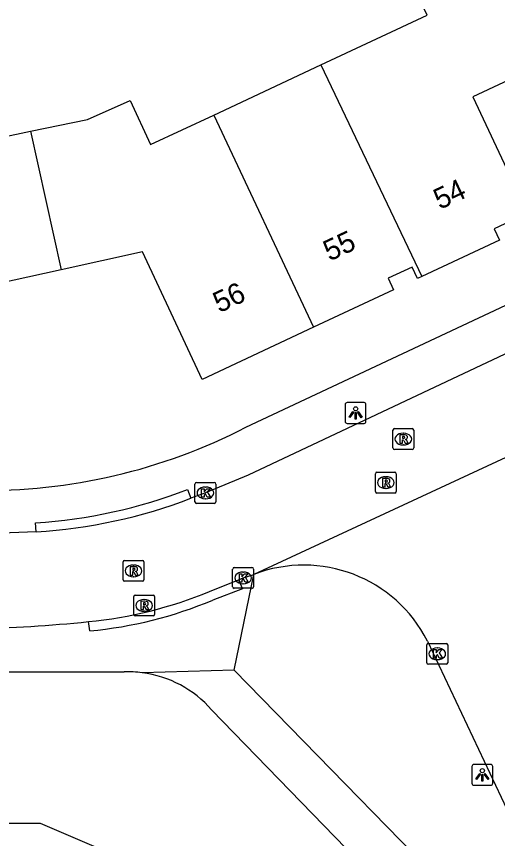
# Model space of a CAD drawing. Extents: x 162880 to 165536, y 384011 to 385179.
# Drawn here: x 163852.88 to 163875.95, y 384301.21 to 384340.61 of the extents above; entities that cross this region are included whole.
import ezdxf

# ---------------------------------------------------------------- set-up
doc = ezdxf.new("R2010")
doc.units = 0
for name, color, linetype in [('IMGEO_Kolk', 7, 'Continuous'), ('IMGEO_Lichtpunt', 7, 'Continuous'), ('IMGEO_Pand', 7, 'Continuous'), ('IMGEO_Pand_nummerreeks', 7, 'Continuous'), ('IMGEO_Rijbaan_lokaal_gesloten', 7, 'Continuous'), ('IMGEO_Rioolput', 7, 'Continuous'), ('IMGEO_Voetpad_open', 7, 'Continuous')]:
    doc.layers.add(name, color=color, linetype=linetype)

msp = doc.modelspace()

# ---------------------------------------------------------------- linework, layer by layer
at = {"layer": 'IMGEO_Kolk'}
for p, q in [((163861.438, 384317.351), (163861.438, 384318.203)), ((163861.513, 384318.277), (163862.365, 384318.277)), ((163861.926, 384318.057), (163861.951, 384318.057)), ((163862.439, 384318.203), (163862.439, 384317.351)), ((163862.365, 384317.277), (163861.513, 384317.277)), ((163861.949, 384317.497), (163861.924, 384317.497)), ((163863.246, 384313.28), (163863.246, 384314.132)), ((163863.321, 384314.206), (163864.173, 384314.206)), ((163864.247, 384314.132), (163864.247, 384313.28)), ((163863.734, 384313.986), (163863.759, 384313.986)), ((163863.757, 384313.426), (163863.732, 384313.426)), ((163864.173, 384313.206), (163863.321, 384313.206)), ((163872.558, 384309.641), (163872.558, 384310.493)), ((163872.633, 384310.567), (163873.485, 384310.567)), ((163873.559, 384310.493), (163873.559, 384309.641)), ((163873.046, 384310.347), (163873.071, 384310.347)), ((163873.069, 384309.787), (163873.044, 384309.787)), ((163873.485, 384309.567), (163872.633, 384309.567))]:
    msp.add_line(p, q, dxfattribs=at)
for points in [[(163861.438, 384317.351), (163861.438, 384318.203)], [(163861.513, 384318.277), (163862.365, 384318.277)], [(163861.759, 384317.977), (163861.882, 384317.977), (163861.882, 384317.826), (163862.012, 384317.977), (163862.176, 384317.977), (163862.03, 384317.826), (163862.183, 384317.577), (163862.031, 384317.577), (163861.946, 384317.741), (163861.882, 384317.674), (163861.882, 384317.577), (163861.759, 384317.577), (163861.759, 384317.977)], [(163862.439, 384318.203), (163862.439, 384317.351)], [(163862.365, 384317.277), (163861.513, 384317.277)], [(163863.246, 384313.28), (163863.246, 384314.132)], [(163863.321, 384314.206), (163864.173, 384314.206)], [(163864.247, 384314.132), (163864.247, 384313.28)], [(163863.567, 384313.906), (163863.69, 384313.906), (163863.69, 384313.755), (163863.82, 384313.906), (163863.984, 384313.906), (163863.838, 384313.755), (163863.991, 384313.506), (163863.839, 384313.506), (163863.754, 384313.67), (163863.69, 384313.603), (163863.69, 384313.506), (163863.567, 384313.506), (163863.567, 384313.906)], [(163864.173, 384313.206), (163863.321, 384313.206)], [(163872.558, 384309.641), (163872.558, 384310.493)], [(163872.633, 384310.567), (163873.485, 384310.567)], [(163873.559, 384310.493), (163873.559, 384309.641)], [(163872.879, 384310.267), (163873.002, 384310.267), (163873.002, 384310.116), (163873.132, 384310.267), (163873.296, 384310.267), (163873.15, 384310.116), (163873.303, 384309.867), (163873.151, 384309.867), (163873.066, 384310.031), (163873.002, 384309.964), (163873.002, 384309.867), (163872.879, 384309.867), (163872.879, 384310.267)], [(163873.485, 384309.567), (163872.633, 384309.567)]]:
    msp.add_lwpolyline(points, dxfattribs=at)
for centre, start, end in [((163861.515, 384318.201), 91.552, 178.448), ((163861.515, 384318.201), 91.552, 178.448), ((163862.363, 384318.201), 1.552, 88.448), ((163862.363, 384318.201), 1.552, 88.448), ((163861.515, 384317.353), 181.552, 268.448), ((163861.515, 384317.353), 181.552, 268.448), ((163862.363, 384317.353), 271.552, 358.448), ((163862.363, 384317.353), 271.552, 358.448), ((163863.323, 384314.13), 91.552, 178.448), ((163863.323, 384314.13), 91.552, 178.448), ((163864.171, 384314.13), 1.552, 88.448), ((163864.171, 384314.13), 1.552, 88.448), ((163863.323, 384313.282), 181.552, 268.448), ((163863.323, 384313.282), 181.552, 268.448), ((163864.171, 384313.282), 271.552, 358.448), ((163864.171, 384313.282), 271.552, 358.448), ((163872.635, 384310.491), 91.552, 178.448), ((163872.635, 384310.491), 91.552, 178.448), ((163873.483, 384310.491), 1.552, 88.448), ((163873.483, 384310.491), 1.552, 88.448), ((163872.635, 384309.643), 181.552, 268.448), ((163872.635, 384309.643), 181.552, 268.448), ((163873.483, 384309.643), 271.552, 358.448), ((163873.483, 384309.643), 271.552, 358.448)]:
    msp.add_arc(centre, 0.0765, start, end, dxfattribs=at)
for centre, major_axis, ratio, start_param, end_param in [((163861.925, 384317.777), (-0.387, 0.002), 0.722429, 4.712389, 7.853982), ((163861.95, 384317.777), (-0.39, 0.002), 0.717154, 1.570796, 4.712389), ((163863.733, 384313.706), (-0.387, 0.002), 0.722429, 4.712389, 7.853982), ((163863.758, 384313.706), (-0.39, 0.002), 0.717154, 1.570796, 4.712389), ((163873.045, 384310.067), (-0.387, 0.002), 0.722429, 4.712389, 7.853982), ((163873.07, 384310.067), (-0.39, 0.002), 0.717154, 1.570796, 4.712389)]:
    msp.add_ellipse(centre, major_axis=major_axis, ratio=ratio, start_param=start_param, end_param=end_param, dxfattribs=at)
at = {"layer": 'IMGEO_Lichtpunt'}
for p, q in [((163868.642, 384322.011), (163868.642, 384321.204)), ((163868.642, 384322.011), (163868.642, 384321.204)), ((163869.544, 384322.106), (163868.736, 384322.106)), ((163869.544, 384322.106), (163868.736, 384322.106)), ((163869.638, 384321.204), (163869.638, 384322.011)), ((163869.638, 384321.204), (163869.638, 384322.011)), ((163868.736, 384321.11), (163869.544, 384321.11)), ((163868.736, 384321.11), (163869.544, 384321.11)), ((163874.721, 384304.669), (163874.721, 384303.862)), ((163874.721, 384304.669), (163874.721, 384303.862)), ((163875.623, 384304.764), (163874.815, 384304.764)), ((163875.623, 384304.764), (163874.815, 384304.764)), ((163875.717, 384303.862), (163875.717, 384304.669)), ((163875.717, 384303.862), (163875.717, 384304.669)), ((163874.815, 384303.768), (163875.623, 384303.768)), ((163874.815, 384303.768), (163875.623, 384303.768))]:
    msp.add_line(p, q, dxfattribs=at)
for points in [[(163869.016, 384321.675), (163869.055, 384321.647), (163868.867, 384321.385), (163868.829, 384321.412), (163869.016, 384321.675)], [(163869.118, 384321.627), (163869.165, 384321.627), (163869.165, 384321.305), (163869.118, 384321.305), (163869.118, 384321.627)], [(163869.228, 384321.647), (163869.266, 384321.674), (163869.453, 384321.412), (163869.414, 384321.384), (163869.228, 384321.647)], [(163875.095, 384304.333), (163875.134, 384304.305), (163874.946, 384304.043), (163874.908, 384304.07), (163875.095, 384304.333)], [(163875.197, 384304.285), (163875.244, 384304.285), (163875.244, 384303.963), (163875.197, 384303.963), (163875.197, 384304.285)], [(163875.307, 384304.305), (163875.345, 384304.332), (163875.532, 384304.07), (163875.493, 384304.042), (163875.307, 384304.305)]]:
    msp.add_lwpolyline(points, dxfattribs=at)
for centre in [(163869.141, 384321.809), (163875.22, 384304.467)]:
    msp.add_circle(centre, 0.0994, dxfattribs=at)
for centre, start, end in [((163868.736, 384322.011), 90, 180), ((163868.736, 384322.011), 90, 180), ((163869.544, 384322.011), 0, 90), ((163869.544, 384322.011), 0, 90), ((163868.736, 384321.204), 180, 270), ((163868.736, 384321.204), 180, 270), ((163869.544, 384321.204), 270, 0), ((163869.544, 384321.204), 270, 360), ((163874.815, 384304.669), 90, 180), ((163874.815, 384304.669), 90, 180), ((163875.623, 384304.669), 0, 90), ((163875.623, 384304.669), 0, 90), ((163874.815, 384303.862), 180, 270), ((163874.815, 384303.862), 180, 270), ((163875.623, 384303.862), 270, 0), ((163875.623, 384303.862), 270, 360)]:
    msp.add_arc(centre, 0.0946, start, end, dxfattribs=at)
at = {"layer": 'IMGEO_Pand'}
for points in [[(163867.481, 384338.294), (163872.569, 384340.676), (163871.581, 384342.787), (163873.082, 384343.496), (163874.574, 384344.201)], [(163862.345, 384335.889), (163867.481, 384338.294)], [(163867.481, 384338.294), (163872.318, 384328.154)], [(163877.472, 384338.021), (163874.764, 384336.753), (163877.382, 384331.186), (163875.787, 384330.441), (163876.041, 384329.897), (163872.318, 384328.154)], [(163853.547, 384335.107), (163856.283, 384335.682), (163858.324, 384336.58), (163859.311, 384334.469), (163862.345, 384335.889)], [(163862.345, 384335.889), (163867.129, 384325.724)], [(163845.313, 384332.091), (163850.472, 384332.091), (163850.471, 384334.461), (163853.547, 384335.107)], [(163853.547, 384335.107), (163855.03, 384328.471)], [(163867.129, 384325.724), (163861.777, 384323.218), (163858.915, 384329.331), (163855.03, 384328.471)], [(163872.318, 384328.154), (163872.102, 384328.053), (163871.848, 384328.597), (163870.707, 384328.063), (163870.961, 384327.518), (163867.129, 384325.724)], [(163855.03, 384328.471), (163851.161, 384327.615), (163851.16, 384320.865), (163845.333, 384320.866)], [(163846.47, 384306.152), (163852.357, 384306.156), (163852.36, 384301.956), (163854.02, 384301.957), (163856.929, 384300.707)]]:
    msp.add_lwpolyline(points, dxfattribs=at)
at = {"layer": 'IMGEO_Rijbaan_lokaal_gesloten'}
for points in [[(163879.615, 384325.991), (163863.997, 384318.625), (163861.94, 384317.777), (163861.247, 384317.522)], [(163879.48, 384320.926), (163864.258, 384313.87)], [(163853.829, 384315.916), (163850.892, 384315.8), (163849.869, 384315.76), (163846.65, 384315.767), (163833.677, 384315.759)], [(163862.135, 384313.051), (163863.528, 384313.607)], [(163863.528, 384313.607), (163863.746, 384313.708), (163864.258, 384313.87)], [(163872.582, 384310.677), (163878.295, 384298.593)]]:
    msp.add_lwpolyline(points, dxfattribs=at)
for centre, radius, start, end in [((163852.345, 384340.706), 24.834, 273.4262, 291.0059), ((163866.657, 384307.676), 6.642, 26.8577, 111.1697), ((163854.346, 384332.034), 20.519, 275.5367, 292.3082), ((163850.172, 384369.286), 58.002, 270.61824, 276.09038)]:
    msp.add_arc(centre, radius, start, end, dxfattribs=at)
at = {"layer": 'IMGEO_Rioolput'}
for p, q in [((163870.929, 384319.933), (163870.929, 384320.785)), ((163871.004, 384320.859), (163871.856, 384320.859)), ((163871.93, 384320.785), (163871.93, 384319.933)), ((163871.417, 384320.639), (163871.442, 384320.639)), ((163871.44, 384320.079), (163871.415, 384320.079)), ((163871.856, 384319.859), (163871.004, 384319.859)), ((163870.167, 384318.774), (163871.019, 384318.774)), ((163870.092, 384317.848), (163870.092, 384318.7)), ((163870.58, 384318.554), (163870.605, 384318.554)), ((163871.093, 384318.7), (163871.093, 384317.848)), ((163870.603, 384317.994), (163870.578, 384317.994)), ((163871.019, 384317.774), (163870.167, 384317.774)), ((163857.992, 384313.617), (163857.992, 384314.469)), ((163858.067, 384314.543), (163858.919, 384314.543)), ((163858.993, 384314.469), (163858.993, 384313.617)), ((163858.48, 384314.323), (163858.505, 384314.323)), ((163858.503, 384313.763), (163858.478, 384313.763)), ((163858.919, 384313.543), (163858.067, 384313.543)), ((163858.577, 384312.884), (163859.429, 384312.884)), ((163858.502, 384311.958), (163858.502, 384312.81)), ((163858.99, 384312.664), (163859.015, 384312.664)), ((163859.503, 384312.81), (163859.503, 384311.958)), ((163859.013, 384312.104), (163858.988, 384312.104)), ((163859.429, 384311.884), (163858.577, 384311.884))]:
    msp.add_line(p, q, dxfattribs=at)
for points in [[(163870.929, 384319.933), (163870.929, 384320.785)], [(163871.004, 384320.859), (163871.856, 384320.859)], [(163871.93, 384320.785), (163871.93, 384319.933)], [(163871.518, 384320.557), (163871.266, 384320.559), (163871.266, 384320.159)], [(163871.266, 384320.159), (163871.39, 384320.159), (163871.39, 384320.321), (163871.401, 384320.321)], [(163871.444, 384320.478), (163871.39, 384320.478), (163871.39, 384320.397)], [(163871.39, 384320.397), (163871.442, 384320.397)], [(163871.448, 384320.292), (163871.519, 384320.159), (163871.659, 384320.159), (163871.594, 384320.285)], [(163871.856, 384319.859), (163871.004, 384319.859)], [(163870.167, 384318.774), (163871.019, 384318.774)], [(163870.092, 384317.848), (163870.092, 384318.7)], [(163870.681, 384318.472), (163870.429, 384318.474), (163870.429, 384318.074)], [(163870.607, 384318.393), (163870.553, 384318.393), (163870.553, 384318.312)], [(163871.093, 384318.7), (163871.093, 384317.848)], [(163870.429, 384318.074), (163870.553, 384318.074), (163870.553, 384318.236), (163870.564, 384318.236)], [(163870.553, 384318.312), (163870.605, 384318.312)], [(163870.611, 384318.207), (163870.682, 384318.074), (163870.822, 384318.074), (163870.757, 384318.2)], [(163871.019, 384317.774), (163870.167, 384317.774)], [(163857.992, 384313.617), (163857.992, 384314.469)], [(163858.067, 384314.543), (163858.919, 384314.543)], [(163858.993, 384314.469), (163858.993, 384313.617)], [(163858.581, 384314.241), (163858.329, 384314.243), (163858.329, 384313.843)], [(163858.329, 384313.843), (163858.453, 384313.843), (163858.453, 384314.005), (163858.464, 384314.005)], [(163858.507, 384314.162), (163858.453, 384314.162), (163858.453, 384314.081)], [(163858.453, 384314.081), (163858.505, 384314.081)], [(163858.511, 384313.976), (163858.582, 384313.843), (163858.722, 384313.843), (163858.657, 384313.969)], [(163858.919, 384313.543), (163858.067, 384313.543)], [(163858.577, 384312.884), (163859.429, 384312.884)], [(163858.502, 384311.958), (163858.502, 384312.81)], [(163859.091, 384312.582), (163858.839, 384312.584), (163858.839, 384312.184)], [(163859.017, 384312.503), (163858.963, 384312.503), (163858.963, 384312.422)], [(163859.503, 384312.81), (163859.503, 384311.958)], [(163858.839, 384312.184), (163858.963, 384312.184), (163858.963, 384312.346), (163858.974, 384312.346)], [(163858.963, 384312.422), (163859.015, 384312.422)], [(163859.021, 384312.317), (163859.092, 384312.184), (163859.232, 384312.184), (163859.167, 384312.31)], [(163859.429, 384311.884), (163858.577, 384311.884)]]:
    msp.add_lwpolyline(points, dxfattribs=at)
for centre, radius, start, end in [((163871.006, 384320.783), 0.0765, 91.552, 178.448), ((163871.006, 384320.783), 0.0765, 91.552, 178.448), ((163871.854, 384320.783), 0.0765, 1.552, 88.448), ((163871.854, 384320.783), 0.0765, 1.552, 88.448), ((163871.4, 384320.268), 0.0533, 26.0293, 88.6989), ((163871.426, 384320.586), 0.19, 274.7715, 282.9687), ((163871.45, 384320.382), 0.0964, 77.0061, 93.1865), ((163871.464, 384320.439), 0.0378, 276.6634, 79.6772), ((163871.517, 384320.447), 0.109, 350.3612, 89.416), ((163871.515, 384320.447), 0.112, 277.5842, 350.9817), ((163871.499, 384320.232), 0.108, 29.5134, 73.7905), ((163871.006, 384319.935), 0.0765, 181.552, 268.448), ((163871.006, 384319.935), 0.0765, 181.552, 268.448), ((163871.854, 384319.935), 0.0765, 271.552, 358.448), ((163871.854, 384319.935), 0.0765, 271.552, 358.448), ((163870.169, 384318.698), 0.0765, 91.552, 178.448), ((163870.169, 384318.698), 0.0765, 91.552, 178.448), ((163871.017, 384318.698), 0.0765, 1.552, 88.448), ((163871.017, 384318.698), 0.0765, 1.552, 88.448), ((163870.613, 384318.297), 0.0964, 77.0061, 93.1865), ((163870.627, 384318.354), 0.0378, 276.6634, 79.6772), ((163870.68, 384318.362), 0.109, 350.3612, 89.416), ((163870.678, 384318.362), 0.112, 277.5842, 350.9817), ((163870.563, 384318.183), 0.0533, 26.0293, 88.6989), ((163870.589, 384318.501), 0.19, 274.7715, 282.9687), ((163870.662, 384318.147), 0.108, 29.5134, 73.7905), ((163870.169, 384317.85), 0.0765, 181.552, 268.448), ((163870.169, 384317.85), 0.0765, 181.552, 268.448), ((163871.017, 384317.85), 0.0765, 271.552, 358.448), ((163871.017, 384317.85), 0.0765, 271.552, 358.448), ((163858.069, 384314.467), 0.0765, 91.552, 178.448), ((163858.069, 384314.467), 0.0765, 91.552, 178.448), ((163858.917, 384314.467), 0.0765, 1.552, 88.448), ((163858.917, 384314.467), 0.0765, 1.552, 88.448), ((163858.463, 384313.952), 0.0533, 26.0293, 88.6989), ((163858.489, 384314.27), 0.19, 274.7715, 282.9687), ((163858.513, 384314.066), 0.0964, 77.0061, 93.1865), ((163858.527, 384314.123), 0.0378, 276.6634, 79.6772), ((163858.58, 384314.131), 0.109, 350.3612, 89.416), ((163858.578, 384314.131), 0.112, 277.5842, 350.9817), ((163858.562, 384313.916), 0.108, 29.5134, 73.7905), ((163858.069, 384313.619), 0.0765, 181.552, 268.448), ((163858.069, 384313.619), 0.0765, 181.552, 268.448), ((163858.917, 384313.619), 0.0765, 271.552, 358.448), ((163858.917, 384313.619), 0.0765, 271.552, 358.448), ((163858.579, 384312.808), 0.0765, 91.552, 178.448), ((163858.579, 384312.808), 0.0765, 91.552, 178.448), ((163859.427, 384312.808), 0.0765, 1.552, 88.448), ((163859.427, 384312.808), 0.0765, 1.552, 88.448), ((163858.999, 384312.611), 0.19, 274.7715, 282.9687), ((163859.023, 384312.407), 0.0964, 77.0061, 93.1865), ((163859.037, 384312.464), 0.0378, 276.6634, 79.6772), ((163859.09, 384312.472), 0.109, 350.3612, 89.416), ((163859.088, 384312.472), 0.112, 277.5842, 350.9817), ((163858.973, 384312.293), 0.0533, 26.0293, 88.6989), ((163859.072, 384312.257), 0.108, 29.5134, 73.7905), ((163858.579, 384311.96), 0.0765, 181.552, 268.448), ((163858.579, 384311.96), 0.0765, 181.552, 268.448), ((163859.427, 384311.96), 0.0765, 271.552, 358.448), ((163859.427, 384311.96), 0.0765, 271.552, 358.448)]:
    msp.add_arc(centre, radius, start, end, dxfattribs=at)
for centre, major_axis, ratio, start_param, end_param in [((163871.416, 384320.359), (-0.387, 0.002), 0.722429, 4.712389, 7.853982), ((163871.441, 384320.359), (-0.39, 0.002), 0.717154, 1.570796, 4.712389), ((163870.579, 384318.274), (-0.387, 0.002), 0.722429, 4.712389, 7.853982), ((163870.604, 384318.274), (-0.39, 0.002), 0.717154, 1.570796, 4.712389), ((163858.479, 384314.043), (-0.387, 0.002), 0.722429, 4.712389, 7.853982), ((163858.504, 384314.043), (-0.39, 0.002), 0.717154, 1.570796, 4.712389), ((163858.989, 384312.384), (-0.387, 0.002), 0.722429, 4.712389, 7.853982), ((163859.014, 384312.384), (-0.39, 0.002), 0.717154, 1.570796, 4.712389)]:
    msp.add_ellipse(centre, major_axis=major_axis, ratio=ratio, start_param=start_param, end_param=end_param, dxfattribs=at)
at = {"layer": 'IMGEO_Voetpad_open'}
for points in [[(163863.881, 384320.929), (163893.758, 384334.936)], [(163861.087, 384317.944), (163861.247, 384317.522)], [(163853.829, 384315.916), (163853.799, 384316.351)], [(163863.528, 384313.607), (163863.711, 384313.189), (163862.293, 384312.644)], [(163863.321, 384309.287), (163864.258, 384313.87)], [(163856.395, 384311.17), (163856.326, 384311.611)], [(163863.321, 384309.287), (163858.909, 384309.16)], [(163878.295, 384298.593), (163875.964, 384296.339), (163863.321, 384309.287)], [(163801.871, 384309.184), (163850.754, 384309.197), (163858.049, 384309.199)], [(163862.239, 384307.377), (163899.33, 384269.205)]]:
    msp.add_lwpolyline(points, dxfattribs=at)
for centre, radius, start, end in [((163851.374, 384345.148), 27.258, 269.0783, 297.3115), ((163852.299, 384340.683), 24.378, 273.5283, 291.1311), ((163854.566, 384331.024), 19.938, 275.2622, 292.8011), ((163858.24, 384303.908), 5.294, 82.74, 92.067), ((163858.245, 384303.919), 5.283, 40.8873, 82.7804)]:
    msp.add_arc(centre, radius, start, end, dxfattribs=at)

# ---------------------------------------------------------------- texts
at = {"layer": 'IMGEO_Pand_nummerreeks'}
for s, p in [('54', (163873.177, 384331.338)), ('55', (163867.89, 384328.862)), ('56', (163862.604, 384326.387))]:
    msp.add_text(s, height=1, rotation=25.0905, dxfattribs=at).set_placement(p)

doc.saveas('drawing.dxf')
